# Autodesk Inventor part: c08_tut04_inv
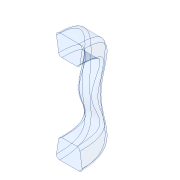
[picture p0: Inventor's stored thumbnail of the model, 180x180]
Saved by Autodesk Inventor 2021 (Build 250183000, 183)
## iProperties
Created: 2015-03
Part Number: c08_tut04_inv
Material: Generic
Document SubType Name: Modeling
Designer: Sandeep
Density: 1 g/cm^3
Appearance: Blue - Glazing
Mass: 996.637 g
Surface Area: 881.078 cm^2
Volume: 996.637 cm^3
Author: Sandeep
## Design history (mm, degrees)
sketch "Sketch1"
  geometry: L1 (-20, 50.541)-(20, 50.541); L2 (30, 60.541)-(30, 70.541); L3 (-30, 60.541)-(-30, 70.541); L4 (0, -9.695)-(0, 120.745); L5 (0, 82)-(-105.666, 82); A1 r 45 centre (0, 37) between (30, 70.541) and (-30, 70.541); A2 r 10 centre (-20, 60.541) between (-30, 60.541) and (-20, 50.541); A3 r 10 centre (20, 60.541) between (20, 50.541) and (30, 60.541); 2 further points
  constraints: 10 end point, 7 point on circle, 5 point on line, 4 tangent, 3 centre point, 2 horizontal, 2 vertical, 1 perpendicular, 1 other
  dimensions: "d0" = 60 distance between parallel lines of L2 L3; "d2" = 20 distance of point (30, 50.541) L2.end; "d3" = 45 radius of A1; "d4" = 10 radius of A2; "d5" = 10 radius of A3; "d22" = 82 distance from line of point (0, 0) L5
sketch "Sketch2"
  geometry: L1 (30.844, 175)-(-30.844, 175); L2 (-40.728, 163.479)-(-33.805, 118.479); L3 (-23.921, 110)-(23.921, 110); L4 (33.805, 118.479)-(40.728, 163.479); L5 (0, 0)-(0, 325.346); A1 r 10 centre (30.844, 165) between (40.728, 163.479) and (30.844, 175); A2 r 10 centre (-30.844, 165) between (-30.844, 175) and (-40.728, 163.479); A3 r 10 centre (-23.921, 120) between (-33.805, 118.479) and (-23.921, 110); A4 r 10 centre (23.921, 120) between (23.921, 110) and (33.805, 118.479); 4 further points
  constraints: 10 end point, 8 point on circle, 8 point on line, 8 tangent, 4 centre point, 3 equal radius, 1 horizontal, 1 parallel, 1 vertical, 1 other
  dimensions: "d6" = 65 distance of point (-32.5, 110) point (32.5, 110); "d7" = 65 distance between parallel lines of L1 L3; "d8" = 85 distance of point (42.5, 175) point (-42.5, 175); "d9" = 175 distance from line of L5.start L1; "d10" = 10 radius of A1
loft "Loft2" sketch "Sketch1", "Sketch2" dims "d23" = 50, "d24" = 90 deg, "d25" = 0, "d26" = 90 deg, "d27" = 50, "d28" = 90 deg
body "Solid2"
sketch "Sketch3"
  geometry: L1 (23.921, -110)-(-23.921, -110); L2 (-33.805, -118.479)-(-40.728, -163.479); L3 (-30.844, -175)-(30.844, -175); L4 (40.728, -163.479)-(33.805, -118.479); L5 (0, 0)-(0, -235.653); A1 r 10 centre (-30.844, -165) between (-40.728, -163.479) and (-30.844, -175); A2 r 10 centre (30.844, -165) between (30.844, -175) and (40.728, -163.479); A3 r 10 centre (23.921, -120) between (33.805, -118.479) and (23.921, -110); A4 r 10 centre (-23.921, -120) between (-23.921, -110) and (-33.805, -118.479); 4 further points
  constraints: 10 end point, 8 point on circle, 8 point on line, 8 tangent, 4 centre point, 3 equal radius, 1 horizontal, 1 parallel, 1 vertical, 1 other
  dimensions: "d11" = 65 distance of point (32.5, -110) point (-32.5, -110); "d12" = 85 distance of point (-42.5, -175) point (42.5, -175); "d13" = 65 distance between parallel lines of L1 L3; "d14" = 175 distance from line of L5.start L3; "d15" = 10 radius of A1
